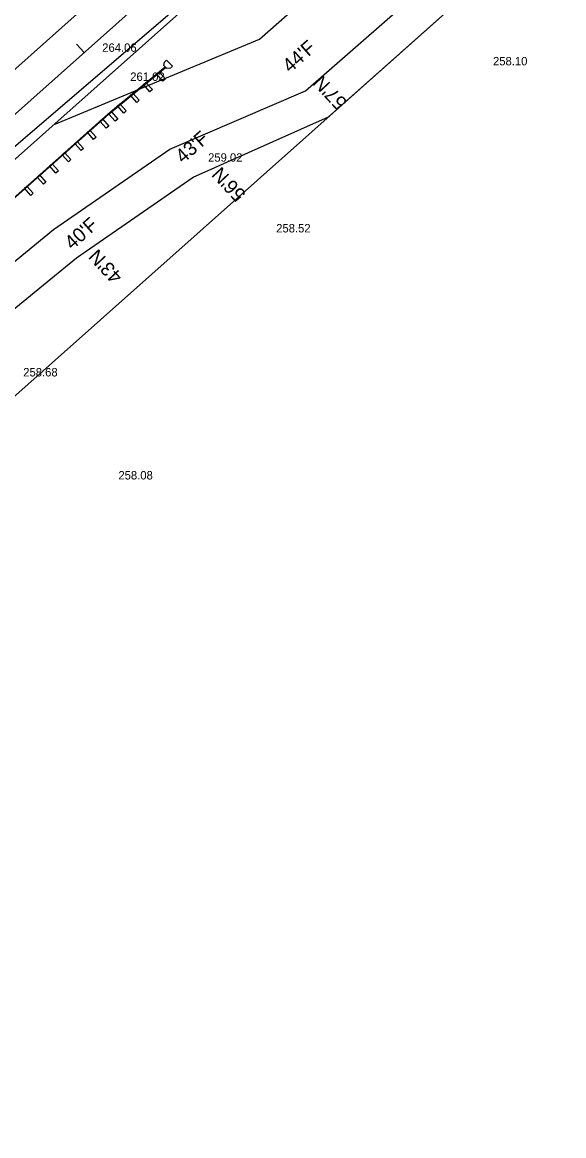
# Model space of a CAD drawing. Extents: x 49683 to 58852, y 49525 to 54803.
# Drawn here: x 54939.2 to 55132.3, y 52384.9 to 52781.8 of the extents above; entities that cross this region are included whole.
import ezdxf

# ---------------------------------------------------------------- set-up
doc = ezdxf.new("R2010")
doc.units = 0
for name, color, linetype in [('Level 11', 7, 'Continuous'), ('Level 13', 7, 'Continuous'), ('Level 18', 7, 'Continuous'), ('Level 19', 7, 'Continuous'), ('Level 20', 7, 'Continuous'), ('Level 27', 7, 'Continuous'), ('Level 32', 7, 'Continuous'), ('Level 33', 7, 'Continuous'), ('Level 48', 7, 'Continuous')]:
    doc.layers.add(name, color=color, linetype=linetype)

msp = doc.modelspace()

# ---------------------------------------------------------------- linework, layer by layer
at = {"layer": 'Level 11'}
msp.add_line((54913.43, 52717.81), (55106.73, 52883.65), dxfattribs=at)
at = {"layer": 'Level 13'}
msp.add_line((55279.53, 53070), (53969.03, 51905.11), dxfattribs=at)
at = {"layer": 'Level 18'}
for p, q in [((55085.77, 52781.37), (55123.14, 52814.59)), ((55040.18, 52757.39), (55077.8, 52790.34)), ((55048.4, 52748.15), (55085.77, 52781.37)), ((54991.76, 52736.61), (55040.18, 52757.39)), ((55000.08, 52726.66), (55048.4, 52748.15)), ((54950.34, 52707.95), (54991.76, 52736.61)), ((54958.55, 52697.87), (55000.08, 52726.66)), ((54911.54, 52676.33), (54950.34, 52707.95)), ((54919.76, 52666.26), (54958.55, 52697.87))]:
    msp.add_line(p, q, dxfattribs=at)
at = {"layer": 'Level 19'}
for p, q in [((54181.77, 52078.16), (56150.85, 53828.45)), ((54961.2, 52770.99), (54958.55, 52773.98))]:
    msp.add_line(p, q, dxfattribs=at)
at = {"layer": 'Level 20'}
for p, q in [((54173.8, 52087.13), (55269.45, 53061.04)), ((54189.74, 52069.19), (55278.86, 53037.3)), ((55023.82, 52775.8), (55098.56, 52842.24)), ((54950.49, 52745.41), (55023.82, 52775.8))]:
    msp.add_line(p, q, dxfattribs=at)
at = {"layer": 'Level 27'}
for p, q in [((54970.77, 52750.06), (54990.12, 52765.92)), ((54970.94, 52749.87), (54990.29, 52765.73)), ((54982.41, 52759.6), (54983.29, 52760.38)), ((54983.29, 52760.38), (54985.55, 52757.84)), ((54987.05, 52763.4), (54987.94, 52764.19)), ((54989.31, 52760.86), (54987.05, 52763.4)), ((54987.94, 52764.19), (54990.2, 52761.65)), ((54990.2, 52761.65), (54989.31, 52760.86)), ((54977.77, 52755.79), (54978.65, 52756.58)), ((54978.65, 52756.58), (54980.91, 52754.03)), ((54984.67, 52757.06), (54982.41, 52759.6)), ((54985.55, 52757.84), (54984.67, 52757.06)), ((54973.12, 52751.98), (54974.01, 52752.77)), ((54974.01, 52752.77), (54976.26, 52750.23)), ((54980.02, 52753.25), (54977.77, 52755.79)), ((54980.91, 52754.03), (54980.02, 52753.25)), ((54196.38, 52061.72), (54970.77, 52750.06)), ((54196.55, 52061.53), (54970.94, 52749.87)), ((54970.06, 52749.09), (54970.94, 52749.87)), ((54972.32, 52746.55), (54970.06, 52749.09)), ((54970.94, 52749.87), (54973.2, 52747.33)), ((54975.38, 52749.44), (54973.12, 52751.98)), ((54976.26, 52750.23), (54975.38, 52749.44)), ((54966.85, 52746.57), (54967.74, 52747.36)), ((54969.11, 52744.03), (54966.85, 52746.57)), ((54967.74, 52747.36), (54969.99, 52744.81)), ((54969.99, 52744.81), (54969.11, 52744.03)), ((54973.2, 52747.33), (54972.32, 52746.55)), ((54962.37, 52742.59), (54963.25, 52743.37)), ((54964.62, 52740.04), (54962.37, 52742.59)), ((54963.25, 52743.37), (54965.51, 52740.83)), ((54965.51, 52740.83), (54964.62, 52740.04)), ((54957.88, 52738.6), (54958.76, 52739.38)), ((54960.14, 52736.06), (54957.88, 52738.6)), ((54958.76, 52739.38), (54961.02, 52736.84)), ((54961.02, 52736.84), (54960.14, 52736.06)), ((54953.4, 52734.61), (54954.28, 52735.4)), ((54955.66, 52732.07), (54953.4, 52734.61)), ((54954.28, 52735.4), (54956.54, 52732.86)), ((54956.54, 52732.86), (54955.66, 52732.07)), ((54948.91, 52730.63), (54949.8, 52731.41)), ((54951.17, 52728.09), (54948.91, 52730.63)), ((54949.8, 52731.41), (54952.05, 52728.87)), ((54952.05, 52728.87), (54951.17, 52728.09)), ((54944.43, 52726.64), (54945.31, 52727.43)), ((54946.69, 52724.1), (54944.43, 52726.64)), ((54945.31, 52727.43), (54947.57, 52724.88)), ((54947.57, 52724.88), (54946.69, 52724.1)), ((54939.94, 52722.65), (54940.83, 52723.44)), ((54942.2, 52720.11), (54939.94, 52722.65)), ((54940.83, 52723.44), (54943.09, 52720.9)), ((54943.09, 52720.9), (54942.2, 52720.11))]:
    msp.add_line(p, q, dxfattribs=at)
msp.add_lwpolyline([(54991.97, 52765.45), (54990.73, 52765.29), (54989.68, 52766.37), (54989.88, 52767.6), (54990.6, 52768.3), (54992.69, 52766.14)], close=True, dxfattribs=at)
at = {"layer": 'Level 33'}
msp.add_line((54231.59, 52022.1), (55608.96, 53246.42), dxfattribs=at)

# ---------------------------------------------------------------- texts
at = {"layer": 'Level 32'}
for s, p in [('264.06', (54967.68, 52771.29)), ('258.10', (55107.05, 52766.46)), ('261.02', (54977.67, 52760.92)), ('259.02', (55005.43, 52732.12)), ('258.52', (55029.72, 52706.91)), ('258.68', (54939.51, 52655.58)), ('258.08', (54973.45, 52618.86))]:
    msp.add_text(s, height=3, dxfattribs=at).set_placement(p)
at = {"layer": 'Level 48'}
for s, rotation, p in [("44'F", 41.6334, (55034.68, 52763.59)), ("57'N", 132.8528, (55055.3, 52753.48)), ("43'F", 41.6334, (54996.51, 52731.27)), ("56'N", 132.8528, (55019.23, 52720.73)), ("40'F", 41.6334, (54956.98, 52700.47)), ("43'N", 132.8528, (54975.25, 52691.44))]:
    msp.add_text(s, height=5, rotation=rotation, dxfattribs=at).set_placement(p)

doc.saveas('drawing.dxf')
